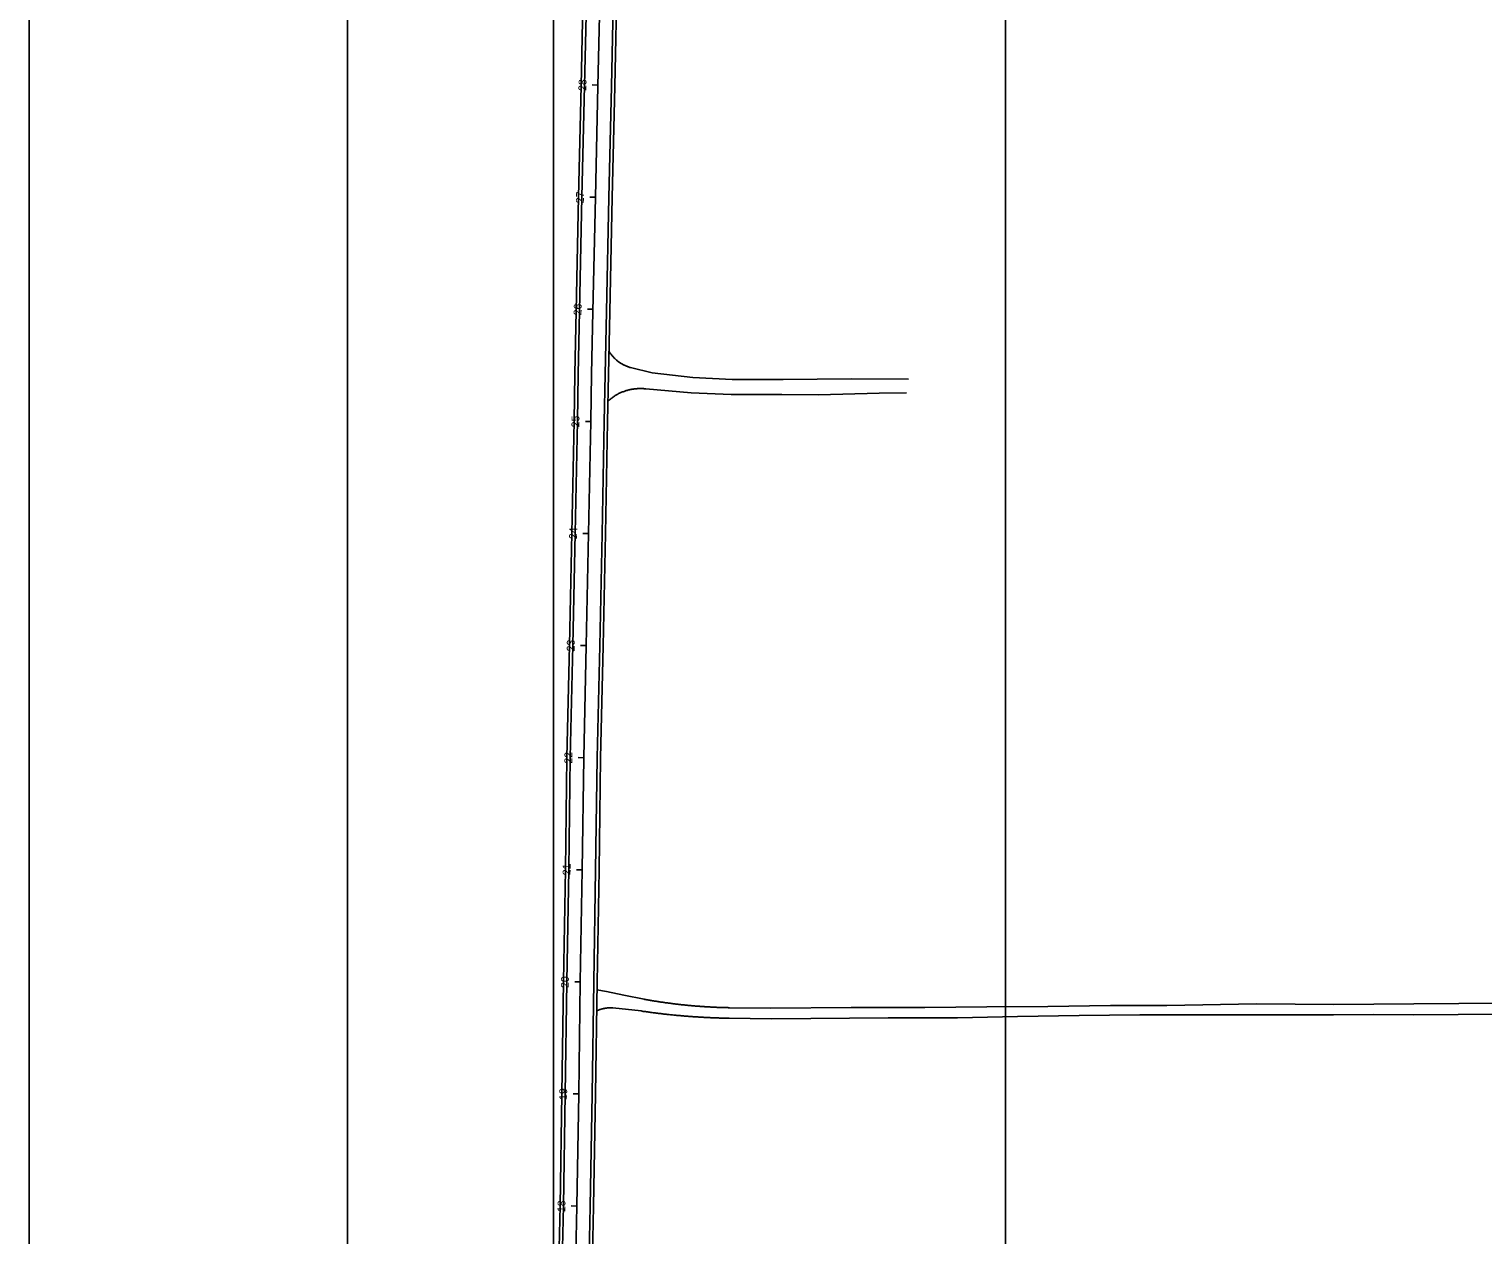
# Model space of a CAD drawing. Extents: x 2318076 to 2324211, y 613525 to 630327.
# Drawn here: x 2318413 to 2319710, y 616710 to 617785 of the extents above; entities that cross this region are included whole.
import ezdxf

# ---------------------------------------------------------------- set-up
doc = ezdxf.new("R2010")
doc.units = 0
for name, color, linetype in [('GE_P_CL_50', 7, 'Continuous'), ('PV_P_EOP', 7, 'Continuous'), ('PV_P_Shoulder', 7, 'Continuous'), ('PV_X_Driveway', 7, 'Continuous'), ('SC_Scratch3', 7, 'Continuous')]:
    doc.layers.add(name, color=color, linetype=linetype)

msp = doc.modelspace()

# ---------------------------------------------------------------- linework, layer by layer
at = {"layer": 'GE_P_CL_50'}
for p, q in [((2318920.2, 617735.2), (2318915.2, 617735.3)), ((2318918, 617635.2), (2318913, 617635.3)), ((2318915.9, 617535.2), (2318910.9, 617535.3)), ((2318913.9, 617435.2), (2318909, 617435.3)), ((2318911.9, 617335.3), (2318906.9, 617335.4)), ((2318909.8, 617235.3), (2318904.8, 617235.4)), ((2318907.6, 617135.3), (2318902.6, 617135.4)), ((2318906, 617035.3), (2318901, 617035.4)), ((2318904.5, 616935.3), (2318899.5, 616935.4)), ((2318903.1, 616835.4), (2318898.1, 616835.4)), ((2318901.4, 616735.4), (2318896.4, 616735.5))]:
    msp.add_line(p, q, dxfattribs=at)
msp.add_lwpolyline([(2318885.9, 615635.5), (2318886.2, 615735.5), (2318887.3, 615835.5), (2318888.6, 615935.5), (2318890, 616035.5), (2318891.3, 616134.6), (2318892.9, 616235.4), (2318894.8, 616335.4), (2318896.2, 616435.4), (2318897.2, 616535.4), (2318899.2, 616635.4), (2318901.4, 616735.4), (2318903.1, 616835.4), (2318904.5, 616935.3), (2318906.2, 617035.3), (2318907.6, 617135.3), (2318909.8, 617235.3), (2318911.9, 617335.3), (2318913.9, 617435.2), (2318914.6, 617477.3), (2318915.8, 617533.4), (2318918, 617635.2), (2318920.2, 617734.2), (2318922.5, 617835.2)], dxfattribs=at)
at = {"layer": 'PV_P_EOP'}
for points in [[(2318873.9, 615635.6), (2318874.2, 615735.6), (2318875.3, 615835.6), (2318876.6, 615935.6), (2318878, 616035.6), (2318879.3, 616134.8), (2318880.9, 616235.7), (2318882.8, 616335.6), (2318884.2, 616435.6), (2318885.2, 616535.6), (2318887.2, 616635.6), (2318889.4, 616735.6), (2318891.1, 616835.5), (2318892.5, 616935.5), (2318894.2, 617035.5), (2318895.6, 617135.5), (2318897.8, 617235.5), (2318899.9, 617335.5), (2318902, 617435.5), (2318902.6, 617477.5), (2318903.8, 617533.7), (2318906, 617635.5), (2318908.2, 617734.5), (2318910.5, 617835.4)], [(2318897.9, 615635.4), (2318898.2, 615735.4), (2318899.3, 615835.3), (2318900.6, 615935.3), (2318902, 616035.3), (2318903.3, 616134.4), (2318904.8, 616235.2), (2318906.8, 616335.2), (2318908.2, 616435.3), (2318909.2, 616535.2), (2318911.2, 616635.1), (2318913.4, 616735.1), (2318915.1, 616835.2), (2318916.5, 616935.2), (2318918.2, 617035.1), (2318919.6, 617135.1), (2318921.8, 617235), (2318923.9, 617335), (2318925.9, 617435), (2318926.6, 617477), (2318927.8, 617533.2), (2318930, 617634.9), (2318932.2, 617733.9), (2318934.5, 617834.9)]]:
    msp.add_lwpolyline(points, dxfattribs=at)
at = {"layer": 'PV_P_Shoulder'}
for points in [[(2318870.9, 615635.6), (2318871.2, 615735.6), (2318872.3, 615835.7), (2318873.6, 615935.7), (2318875, 616035.7), (2318876.3, 616134.8), (2318877.9, 616235.7), (2318879.8, 616335.7), (2318881.2, 616435.6), (2318882.2, 616535.6), (2318884.2, 616635.7), (2318886.4, 616735.7), (2318888.1, 616835.6), (2318889.5, 616935.6), (2318891.2, 617035.6), (2318892.6, 617135.6), (2318894.8, 617235.6), (2318896.9, 617335.6), (2318899, 617435.5), (2318899.6, 617477.6), (2318900.8, 617533.7), (2318903, 617635.5), (2318905.2, 617734.5), (2318907.5, 617835.5)], [(2318900.9, 615635.4), (2318901.2, 615735.4), (2318902.3, 615835.3), (2318903.6, 615935.3), (2318905, 616035.3), (2318906.3, 616134.4), (2318907.8, 616235.2), (2318909.8, 616335.2), (2318911.2, 616435.2), (2318912.2, 616535.2), (2318914.2, 616635.1), (2318916.4, 616735.1), (2318918.1, 616835.1), (2318919.5, 616935.1), (2318921.2, 617035.1), (2318922.6, 617135), (2318924.8, 617235), (2318926.9, 617335), (2318928.9, 617435), (2318929.6, 617477), (2318930.8, 617533.1), (2318933, 617634.9), (2318935.2, 617733.9), (2318937.5, 617834.8)]]:
    msp.add_lwpolyline(points, dxfattribs=at)
at = {"layer": 'PV_X_Driveway'}
for p, q in [((2318919.4, 616928.2), (2318927.9, 616926.7)), ((2318933.5, 616912.1), (2318958.8, 616909.4))]:
    msp.add_line(p, q, dxfattribs=at)
for points in [[(2318949.3, 617483.3), (2318948.7, 617483.4), (2318948.2, 617483.6), (2318947.6, 617483.8), (2318947.1, 617484), (2318946.6, 617484.2), (2318946.1, 617484.4), (2318945.5, 617484.6), (2318945, 617484.8), (2318944.5, 617485), (2318944, 617485.3), (2318943.5, 617485.5), (2318943, 617485.8), (2318942.5, 617486), (2318942, 617486.3), (2318941.5, 617486.6), (2318941, 617486.9), (2318940.5, 617487.2), (2318940.1, 617487.5), (2318939.6, 617487.8), (2318939.1, 617488.1), (2318938.7, 617488.4), (2318938.2, 617488.8), (2318937.8, 617489.1), (2318937.3, 617489.5), (2318936.9, 617489.8), (2318936.5, 617490.2), (2318936, 617490.6), (2318935.6, 617490.9), (2318935.2, 617491.3), (2318934.8, 617491.7), (2318934.4, 617492.1), (2318934, 617492.5), (2318933.7, 617493), (2318933.3, 617493.4), (2318932.9, 617493.8), (2318932.6, 617494.2), (2318932.2, 617494.7), (2318931.9, 617495.1), (2318931.5, 617495.6), (2318931.2, 617496), (2318930.9, 617496.5), (2318930.6, 617497), (2318930.3, 617497.5), (2318930.1, 617497.8)], [(2319197.3, 617472.8), (2319146.1, 617473.3), (2319085.5, 617472.7), (2319039.9, 617472.6), (2319004.9, 617474.5), (2318968.6, 617478.7), (2318949.3, 617483.3)], [(2318929.2, 617453.4), (2318929.7, 617453.8), (2318930.2, 617454.3), (2318930.8, 617454.7), (2318931.4, 617455.2), (2318931.9, 617455.6), (2318932.5, 617456.1), (2318933.1, 617456.5), (2318933.7, 617456.9), (2318934.3, 617457.4), (2318934.9, 617457.8), (2318935.5, 617458.2), (2318936.2, 617458.5), (2318936.8, 617458.9), (2318937.4, 617459.3), (2318938.1, 617459.6), (2318938.7, 617460), (2318939.4, 617460.3), (2318940.1, 617460.6), (2318940.7, 617460.9), (2318941.4, 617461.2), (2318942.1, 617461.5), (2318942.8, 617461.7), (2318943.5, 617462), (2318944.1, 617462.2), (2318944.8, 617462.5), (2318945.5, 617462.7), (2318946.2, 617462.9), (2318947, 617463.1), (2318947.7, 617463.3), (2318948.4, 617463.5), (2318949.1, 617463.6), (2318949.8, 617463.8), (2318950.5, 617463.9), (2318951.3, 617464), (2318952, 617464.1), (2318952.7, 617464.2), (2318953.4, 617464.3), (2318954.2, 617464.4), (2318954.9, 617464.4), (2318955.6, 617464.5), (2318956.4, 617464.5), (2318957.1, 617464.6), (2318957.8, 617464.6), (2318958.6, 617464.6), (2318959.3, 617464.5), (2318960, 617464.5), (2318960.8, 617464.5), (2318961.5, 617464.4), (2318962.2, 617464.4), (2318963, 617464.3)], [(2318963, 617464.3), (2319003.4, 617460.7), (2319039, 617459.3), (2319084.3, 617459.2), (2319117, 617458.8), (2319171.2, 617460.5), (2319195.6, 617460.8)], [(2318961.4, 616919.9), (2318943.4, 616923.5), (2318927.9, 616926.7)], [(2320498.9, 616927.1), (2320436.5, 616926.2), (2320383.8, 616925.9), (2320318, 616925.4), (2320236.6, 616925.5), (2320200.9, 616924.5), (2320104.4, 616924.5), (2320023.7, 616923), (2319951.7, 616921.9), (2319887.6, 616920), (2319809, 616917.2), (2319728.2, 616916.4), (2319647.9, 616915.7), (2319576.6, 616915.1), (2319507.6, 616915.7), (2319427.6, 616914.4), (2319377.5, 616914.4), (2319321.6, 616913.3), (2319267.2, 616913.2), (2319211.7, 616912.6), (2319146.1, 616912.4), (2319074.4, 616912), (2319037.6, 616912.3)], [(2319037.6, 616912.3), (2319036.8, 616912.3), (2319036, 616912.4), (2319035.1, 616912.4), (2319034.3, 616912.4), (2319033.4, 616912.4), (2319032.6, 616912.4), (2319031.7, 616912.5), (2319030.9, 616912.5), (2319030.1, 616912.5), (2319029.2, 616912.5), (2319028.4, 616912.6), (2319027.5, 616912.6), (2319026.7, 616912.6), (2319025.8, 616912.7), (2319025, 616912.7), (2319024.2, 616912.8), (2319023.3, 616912.8), (2319022.5, 616912.8), (2319021.6, 616912.9), (2319020.8, 616912.9), (2319020, 616913), (2319019.1, 616913), (2319018.3, 616913.1), (2319017.4, 616913.1), (2319016.6, 616913.2), (2319015.7, 616913.2), (2319014.9, 616913.3), (2319014.1, 616913.3), (2319013.2, 616913.4), (2319012.4, 616913.4), (2319011.5, 616913.5), (2319010.7, 616913.6), (2319009.9, 616913.6), (2319009, 616913.7), (2319008.2, 616913.8), (2319007.3, 616913.8), (2319006.5, 616913.9), (2319005.7, 616914), (2319004.8, 616914), (2319004, 616914.1), (2319003.1, 616914.2), (2319002.3, 616914.3), (2319001.5, 616914.4), (2319000.6, 616914.4), (2318999.8, 616914.5), (2318999, 616914.6), (2318998.1, 616914.7), (2318997.3, 616914.8), (2318996.4, 616914.9), (2318995.6, 616915), (2318994.8, 616915), (2318993.9, 616915.1), (2318993.1, 616915.2), (2318992.3, 616915.3), (2318991.4, 616915.4), (2318990.6, 616915.5), (2318989.7, 616915.6), (2318988.9, 616915.7), (2318988.1, 616915.8), (2318987.2, 616915.9), (2318986.4, 616916), (2318985.6, 616916.1), (2318984.7, 616916.3), (2318983.9, 616916.4), (2318983.1, 616916.5), (2318982.2, 616916.6), (2318981.4, 616916.7), (2318980.5, 616916.8), (2318979.7, 616916.9), (2318978.9, 616917.1), (2318978, 616917.2), (2318977.2, 616917.3), (2318976.4, 616917.4), (2318975.5, 616917.6), (2318974.7, 616917.7), (2318973.9, 616917.8), (2318973, 616917.9), (2318972.2, 616918.1), (2318971.4, 616918.2), (2318970.6, 616918.3), (2318969.7, 616918.5), (2318968.9, 616918.6), (2318968.1, 616918.8), (2318967.2, 616918.9), (2318966.4, 616919), (2318965.6, 616919.2), (2318964.7, 616919.3), (2318963.9, 616919.5), (2318963.1, 616919.6), (2318962.2, 616919.8), (2318961.4, 616919.9)], [(2318919.1, 616909.4), (2318920.1, 616909.8), (2318920.5, 616910), (2318921, 616910.2), (2318921.4, 616910.4), (2318921.9, 616910.6), (2318922.4, 616910.7), (2318922.8, 616910.9), (2318923.3, 616911), (2318923.8, 616911.2), (2318924.3, 616911.3), (2318924.7, 616911.4), (2318925.2, 616911.5), (2318925.7, 616911.6), (2318926.2, 616911.7), (2318926.7, 616911.8), (2318927.2, 616911.9), (2318927.6, 616912), (2318928.1, 616912), (2318928.6, 616912.1), (2318929.1, 616912.1), (2318929.6, 616912.2), (2318930.1, 616912.2), (2318930.6, 616912.2), (2318931.1, 616912.2), (2318931.6, 616912.2), (2318932.1, 616912.2), (2318932.6, 616912.2), (2318933.1, 616912.2), (2318933.5, 616912.1)], [(2318958.8, 616909.4), (2318959.8, 616909.3), (2318960.7, 616909.1), (2318961.7, 616909), (2318962.6, 616908.9), (2318963.6, 616908.7), (2318964.6, 616908.6), (2318965.5, 616908.4), (2318966.5, 616908.3), (2318967.5, 616908.2), (2318968.4, 616908.1), (2318969.4, 616907.9), (2318970.4, 616907.8), (2318971.3, 616907.7), (2318972.3, 616907.6), (2318973.3, 616907.4), (2318974.2, 616907.3), (2318975.2, 616907.2), (2318976.2, 616907.1), (2318977.1, 616907), (2318978.1, 616906.9), (2318979.1, 616906.7), (2318980, 616906.6), (2318981, 616906.5), (2318982, 616906.4), (2318983, 616906.3), (2318983.9, 616906.2), (2318984.9, 616906.1), (2318985.9, 616906), (2318986.8, 616905.9), (2318987.8, 616905.8), (2318988.8, 616905.7), (2318989.7, 616905.6), (2318990.7, 616905.5), (2318991.7, 616905.4), (2318992.7, 616905.3), (2318993.6, 616905.3), (2318994.6, 616905.2), (2318995.6, 616905.1), (2318996.5, 616905), (2318997.5, 616904.9), (2318998.5, 616904.8), (2318999.5, 616904.8), (2319000.4, 616904.7), (2319001.4, 616904.6), (2319002.4, 616904.5), (2319003.3, 616904.5), (2319004.3, 616904.4), (2319005.3, 616904.3), (2319006.3, 616904.2), (2319007.2, 616904.2), (2319008.2, 616904.1), (2319009.2, 616904.1), (2319010.2, 616904), (2319011.1, 616903.9), (2319012.1, 616903.9), (2319013.1, 616903.8), (2319014, 616903.8), (2319015, 616903.7), (2319016, 616903.7), (2319017, 616903.6), (2319017.9, 616903.6), (2319018.9, 616903.5), (2319019.9, 616903.5), (2319020.9, 616903.4), (2319021.8, 616903.4), (2319022.8, 616903.3), (2319023.8, 616903.3), (2319024.8, 616903.3), (2319025.7, 616903.2), (2319026.7, 616903.2), (2319027.7, 616903.2), (2319028.7, 616903.1), (2319029.6, 616903.1), (2319030.6, 616903.1), (2319031.6, 616903), (2319032.6, 616903), (2319033.5, 616903), (2319034.5, 616903), (2319035.5, 616903), (2319036.5, 616902.9), (2319037.4, 616902.9)], [(2319037.4, 616902.9), (2319074.8, 616902.4), (2319110.2, 616902.8), (2319179.1, 616903.3), (2319241.1, 616903.4), (2319294.5, 616904.6), (2319349.6, 616905.4), (2319403.7, 616906.1), (2319467.6, 616905.9), (2319543.4, 616906.1), (2319576.5, 616905.9), (2319611.9, 616906.2), (2319647.9, 616906.1), (2319727.2, 616906.5)]]:
    msp.add_lwpolyline(points, dxfattribs=at)
at = {"layer": 'SC_Scratch3'}
for p, q in [((2318412.8, 614778.4), (2318412.8, 630327.2)), ((2318696.7, 614778.4), (2318696.7, 630327.2)), ((2318880.5, 614778.4), (2318880.5, 630327.2)), ((2319283.9, 614778.4), (2319283.9, 630327.2))]:
    msp.add_line(p, q, dxfattribs=at)

# ---------------------------------------------------------------- texts
at = {"layer": 'GE_P_CL_50'}
for s, rotation, p in [('28', 88.5144, (2318909.8, 617729.9)), ('27', 88.608, (2318907.6, 617629.7)), ('26', 88.8343, (2318905.5, 617529.8)), ('25', 89.0866, (2318903.6, 617429.9)), ('24', 88.4011, (2318901.5, 617330.2)), ('23', 89.0975, (2318899.4, 617230.1)), ('22', 89.3393, (2318897.3, 617130)), ('21', 88.8736, (2318895.7, 617030.4)), ('20', 89.348, (2318894.2, 616929.9)), ('19', 89.2487, (2318892.7, 616830)), ('18', 88.8336, (2318891.1, 616730))]:
    msp.add_text(s, height=7, rotation=rotation, dxfattribs=at).set_placement(p)

doc.saveas('drawing.dxf')
